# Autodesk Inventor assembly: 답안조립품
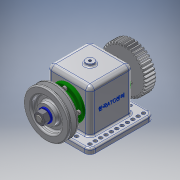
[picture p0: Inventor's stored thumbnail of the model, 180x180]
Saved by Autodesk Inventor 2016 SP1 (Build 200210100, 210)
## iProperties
Created: 2018-11
Part Number: 답안조립품
Material: 일반
Document SubType Name: Assembly
Designer: basic
Author: basic
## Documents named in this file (13)
- C:\Users\basic\Desktop\481108V1004\답안조립품.iam
- C:\Users\basic\Desktop\481108V1004\본체.ipt
- C:\Users\basic\Desktop\481108V1004\481108V1004\축.ipt
- C:\Users\basic\Desktop\481108V1004\481108V1004\베어링 6203.ipt
- C:\Users\basic\Desktop\481108V1004\481108V1004\부시.ipt
- C:\Users\basic\Desktop\481108V1004\481108V1004\커버.ipt
- C:\Users\basic\Desktop\481108V1004\481108V1004\오일 실 26 38 8.ipt
- C:\Users\basic\Desktop\481108V1004\481108V1004\볼트 M4.ipt
- C:\Users\basic\Desktop\481108V1004\481108V1004\키 5x5x12.ipt
- C:\Users\basic\Desktop\481108V1004\481108V1004\V벨트풀리.ipt
- C:\Users\basic\Desktop\481108V1004\481108V1004\스퍼기어.ipt
- C:\Users\basic\Desktop\481108V1004\481108V1004\와셔 12x24.ipt
- C:\Users\basic\Desktop\481108V1004\481108V1004\너트 M12x1.25.ipt
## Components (1 placed, 1 different names)
1. V벨트풀리:1
